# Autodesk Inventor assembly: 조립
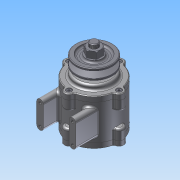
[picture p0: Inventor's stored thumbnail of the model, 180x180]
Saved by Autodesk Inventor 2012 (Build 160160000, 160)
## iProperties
Created: 2015-03
Part Number: 조립
Document SubType Name: Assembly
Designer: net
Author: net
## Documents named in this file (11)
- C:\Users\net\Desktop\450305V1050\조립.iam
- C:\Users\net\Desktop\450305V1050\본체.ipt
- C:\Users\net\Desktop\450305V1050\커버.ipt
- C:\Users\net\Desktop\450305V1050\커버2.ipt
- C:\Users\net\Desktop\450305V1050\베어링 6204.ipt
- C:\Users\net\Desktop\450305V1050\오일실.ipt
- C:\Users\net\Desktop\450305V1050\축.ipt
- C:\Users\net\Desktop\450305V1050\키(4 x 4 x 12).ipt
- C:\Users\net\Desktop\450305V1050\V벨트풀리.ipt
- C:\Users\net\Desktop\450305V1050\M 4 x 12.ipt
- C:\Users\net\Desktop\450305V1050\너트 M12x1.25.ipt
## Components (14 placed, 6 different names)
1. KS B 2023 6204 - 20 x 47 x 14:1
2. KS B 2023 6204 - 20 x 47 x 14:2
3. KS B 2804 D D - 20 32 8:1
4. KS B 1311 (I) 4 x 4 x 12:1
5. 그루브 풀리1:1
6. KS B 1012 클래스 1 일반 - 미터 M12x1.25:1
7. KS B 1003 - 미터 M 4 x 12:1
8. KS B 1003 - 미터 M 4 x 12:2
9. KS B 1003 - 미터 M 4 x 12:3
10. KS B 1003 - 미터 M 4 x 12:4
11. KS B 1003 - 미터 M 4 x 12:5
12. KS B 1003 - 미터 M 4 x 12:6
13. KS B 1003 - 미터 M 4 x 12:7
14. KS B 1003 - 미터 M 4 x 12:8
